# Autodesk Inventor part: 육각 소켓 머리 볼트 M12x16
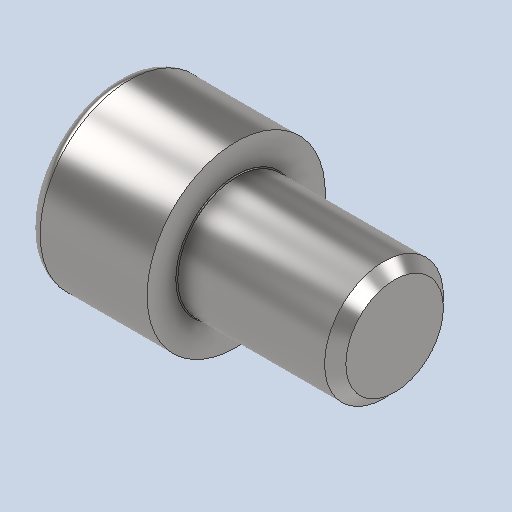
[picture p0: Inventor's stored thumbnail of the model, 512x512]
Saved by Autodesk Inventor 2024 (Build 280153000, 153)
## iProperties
Created: 2024-07
Part Number: 육각 소켓 머리 볼트 M12x16
Material: 강철, 연강
Description: 6각머리 태핑 나사
Document SubType Name: Modeling
Designer: com
Density: 7.85 g/cm^3
Appearance: 기본값
Author: jhkim
Sending System: Autodesk Inventor 2025
Preprocessor: ST-DEVELOPER v20
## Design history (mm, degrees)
feature "Solid1"
node "솔리드1"
